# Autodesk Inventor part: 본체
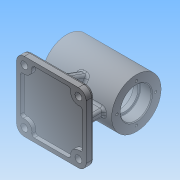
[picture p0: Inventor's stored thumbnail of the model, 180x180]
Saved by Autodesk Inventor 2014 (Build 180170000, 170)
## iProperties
Created: 2019-06
Part Number: 본체
Material: 일반
Document SubType Name: Modeling
Designer: net
Density: 1 g/cm^3
Appearance: 기본값
Author: net
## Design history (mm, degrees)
sketch "스케치1"
  geometry: L1 (-45, 0)-(45, 0); L2 (45, 0)-(45, 32); L3 (45, 32)-(-45, 32); L4 (-45, 32)-(-45, 0); 2 further points
  constraints: 8 end point, 2 parallel, 1 coincident, 1 horizontal, 1 midpoint, 1 perpendicular
  dimensions: "d0" = 90 distance of L2.end L3.end; "d1" = 64 diameter of L3 L1
revolve "회전1" sketch "스케치1" stored, may be unused: angle "d2" = 90 deg
node "작업 평면1"
sketch "스케치2"
  geometry: L1 (-45, 45)-(45, 45); L2 (45, 45)-(45, -45); L3 (45, -45)-(-45, -45); L4 (-45, -45)-(-45, 45); L5 (-45, 45)-(45, -45); L6 (45, 45)-(-45, -45); 1 further point
  constraints: 12 end point, 2 midpoint, 2 parallel, 1 horizontal, 1 perpendicular
  dimensions: "d4" = 90 distance of L1.start L1.end; "d5" = 90 distance of L1.end L2.end
extrude "돌출1" join sketch "스케치2" distance "d6" = 10; taper "d7" = 0 deg
sketch "스케치3"
  geometry: L1 (0, 5)-(-55, 5); L2 (-55, 5)-(-55, -5); L3 (-55, -5)-(0, -5); L4 (0, -5)-(0, 5); L5 (-65, 45)-(-65, -45) reference; L6 (-65, 45)-(-55, 45) reference; L7 (-55, -45)-(-55, 45) reference; L8 (-65, -45)-(-55, -45) reference; C1 r 32 at (0, 0) reference; 2 further points
  constraints: 8 end point, 3 midpoint, 2 parallel, 1 horizontal, 1 horizontal alignment, 1 perpendicular
  dimensions: "d8" = 10 distance of L3.end L1.start
extrude "돌출2" join sketch "스케치3" stored distance "d9" = 70; taper "d10" = 0 deg
sketch "스케치4"
  geometry: L1 (-55, -45)-(-55, 45) reference; L2 (-55, 5)-(-31.607, 5) reference; L3 (-31.607, -5)-(-55, -5) reference; L4 (-55, 35)-(-20, 22.261); L5 (-20, 22.261)-(-20, -22.261); L6 (-20, -22.261)-(-55, -35); L7 (-55, 35)-(-55, -35); 2 further points
  constraints: 8 end point, 2 point on line, 1 collinear, 1 equal length, 1 horizontal alignment, 1 midpoint, 1 perpendicular
  dimensions: "d11" = 10 distance of L4.start L1.end; "d12" = 110 deg angle of L4 L1; "d13" = 35 distance between parallel lines of L1 L5
extrude "돌출3" join sketch "스케치4" stored distance "d14" = 10; taper "d15" = 0 deg
sketch "스케치5"
  geometry: L1 (-45, -32)-(-45, 32) reference; L2 (-45, 32)-(45, 32) reference; L3 (45, -32)-(45, 32) reference; L4 (-45, 0)-(45, 0); L5 (-45, 20)-(-30, 20); L6 (-30, 20)-(-30, 17); L7 (-30, 17)-(-24, 17); L8 (-24, 17)-(-24, 25); L9 (-24, 25)-(24, 25); L10 (24, 25)-(24, 17); L11 (24, 17)-(30, 17); L12 (30, 17)-(30, 20); L13 (30, 20)-(45, 20); L14 (45, 20)-(45, 0); L15 (-45, 20)-(-45, 0); 1 further point
  constraints: 24 end point, 7 parallel, 3 collinear, 3 equal length, 2 midpoint, 2 perpendicular, 2 point on line
  dimensions: "d16" = 15 distance of L5.start L5.end; "d17" = 48 distance of L8.end L9.end; "d18" = 50 diameter of L9 L4; "d19" = 40 diameter of L5 L4; "d20" = 34 diameter of L7 L4
revolve "회전2" sketch "스케치5" stored, may be unused: angle "d21" = 90 deg
node "작업 평면2"
sketch "스케치6"
  geometry: C1 r 5 at (0, 0); 1 further point
  constraints: 1 centre point, 1 coincident
  dimensions: "d23" = 10 diameter of C1
extrude "돌출4" join sketch "스케치6" distance "d24" = 10; taper "d25" = 0 deg
hole "구멍1" diameter "d28" = 4.917; stored, may be unused: countersink angle "d32" = 90 deg, drill point angle "d34" = 118 deg; dims "d29" = 6, "d30" = 4, "d31" = 2, "d33" = 12, "d35" = 10, "d36" = 10
hole "구멍2" diameter "d39" = 9; stored, may be unused: countersink angle "d43" = 90 deg, drill point angle "d45" = 0 deg; dims "d37" = 10, "d38" = 10, "d40" = 6, "d41" = 4, "d42" = 2, "d44" = 10
fillet "모깎기1" dims "d52" = 10
sketch "스케치7"
  geometry: L1 (-40, 40)-(-26.34, 40); L2 (40, 40)-(40, 26.34); L3 (40, -40)-(26.34, -40); L4 (-40, -40)-(-40, -26.34); L5 (-40, 40)-(40, -40); L6 (40, 40)-(-40, -40); L7 (-26.34, 40)-(26.34, 40); L8 (-40, 26.34)-(-40, 40); L9 (26.34, 40)-(40, 40); L10 (40, -26.34)-(40, -40); L11 (26.34, -40)-(-26.34, -40); L12 (-26.34, -40)-(-40, -40); L13 (-40, -26.34)-(-40, 26.34); L14 (40, 26.34)-(40, -26.34); C1 r 4.5 at (-35, 35) reference; C2 r 4.5 at (35, 35) reference; C3 r 4.5 at (-35, -35) reference; C4 r 4.5 at (35, -35) reference; A1 r 10 centre (-35, 35) between (-26.34, 40) and (-40, 26.34); A2 r 10 centre (35, 35) between (40, 26.34) and (27.929, 27.929); A3 r 10 centre (35, -35) between (40, -26.34) and (26.34, -40); A4 r 10 centre (-35, -35) between (-26.34, -40) and (-40, -26.34); A5 r 10 centre (35, 35) between (27.929, 27.929) and (40, 26.34); 1 further point
  constraints: 28 end point, 18 parallel, 11 point on circle, 9 perpendicular, 5 centre point, 4 coincident, 3 horizontal, 2 midpoint, 1 point on line
  dimensions: "d53" = 80 distance of L1.start L2.start; "d54" = 80 distance of L2.start L3.start; "d55" = 20 diameter of A1; "d56" = 20 diameter of A2; "d57" = 20 diameter of A3; "d58" = 20 diameter of A4
extrude "돌출5" cut sketch "스케치7" distance "d59" = 5; taper "d60" = 0 deg
fillet "모깎기2" dims "d61" = 3
fillet "모깎기3" dims "d62" = 3
fillet "모깎기4" dims "d63" = 3
fillet "모깎기5" dims "d64" = 3
fillet "모깎기6" dims "d65" = 2
chamfer "모따기1" distance "d66" = 1; stored, may be unused: second distance "d67" = 2, angle "d68" = 45 deg
fillet "모깎기7" dims "d69" = 3
fillet "모깎기8" dims "d70" = 0.6
sketch "스케치8"
  geometry: C1 r 32 at (0, 0) reference; 1 further point
  constraints: 1 vertical alignment
  dimensions: "d71" = 25 distance of C1.centre point (0, 25)
hole "구멍3" sketch "스케치8" at (0, 25) diameter "d72" = 3.242; stored, may be unused: countersink angle "d76" = 90 deg, drill point angle "d78" = 118 deg; dims "d73" = 7, "d74" = 4, "d75" = 2, "d77" = 9
sketch "스케치10"
  geometry: L1 (70, 0)-(0, 0) reference; L2 (-10, 7)-(-10, 0) reference; 2 further points
  constraints: 1 other
  dimensions: "d86" = 45 distance from line of point (35, 4) L2; "d87" = 4 distance from line of point (35, 4) L1
feature "엠보싱2" sketch "스케치10" dims "d88" = 0.5, "d89" = 0
node "솔리드1"
pattern_linear "직사각형 패턴1" dims "d48" = 70
pattern_circular "원형 패턴1" dims angle "d80" = 360 deg
mirror "대칭1"
node "투영된 루프1"
other parameters: "d3" = -65
